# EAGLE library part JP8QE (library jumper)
JUMPER
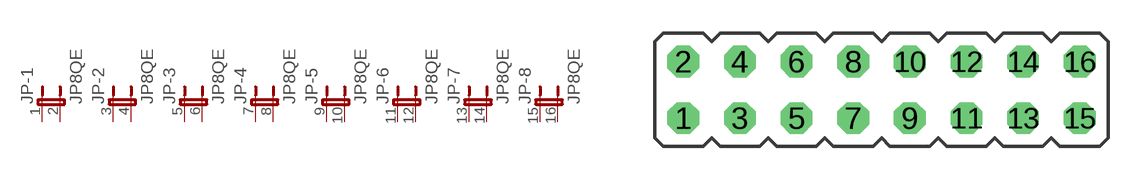
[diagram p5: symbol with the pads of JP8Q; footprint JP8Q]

Designator prefix JP; gates -1=JP2E -2=JP2E -3=JP2E -4=JP2E -5=JP2E -6=JP2E -7=JP2E -8=JP2E

## JP8QE  [JP8Q]
1  -1:1  pas
2  -1:2  pas
3  -2:1  pas
4  -2:2  pas
5  -3:1  pas
6  -3:2  pas
7  -4:1  pas
8  -4:2  pas
9  -5:1  pas
10  -5:2  pas
11  -6:1  pas
12  -6:2  pas
13  -7:1  pas
14  -7:2  pas
15  -8:1  pas
16  -8:2  pas

## Footprint JP8Q (pad centres in mm)
JUMPER
drill 0.914 octagon: 1 -8.89,-1.27; 2 -8.89,1.27; 3 -6.35,-1.27; 4 -6.35,1.27; 5 -3.81,-1.27; 6 -3.81,1.27; 7 -1.27,-1.27; 8 -1.27,1.27; 9 1.27,-1.27; 10 1.27,1.27; 11 3.81,-1.27; 12 3.81,1.27; 13 6.35,-1.27; 14 6.35,1.27; 15 8.89,-1.27; 16 8.89,1.27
